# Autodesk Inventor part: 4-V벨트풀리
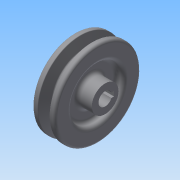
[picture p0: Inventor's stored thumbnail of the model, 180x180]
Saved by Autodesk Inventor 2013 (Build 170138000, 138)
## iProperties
Created: 2015-03
Part Number: 4-V벨트풀리
Material: 일반
Document SubType Name: Modeling
Designer: Administrator
Density: 1 g/cm^3
Author: Administrator
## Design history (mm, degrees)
sketch "스케치1"
  geometry: L1 (0, 0)-(25, 0); L2 (0, 0)-(0, 11); L3 (0, 11)-(6, 11); L4 (6, 11)-(6, 21.5); L5 (6, 21.5)-(0, 21.5); L6 (0, 21.5)-(0, 35.2); L7 (0, 35.2)-(4.675, 35.2); L8 (4.675, 35.2)-(7.426, 26.2); L9 (7.426, 26.2)-(11.574, 26.2); L10 (11.574, 26.2)-(14.325, 35.2); L11 (14.325, 35.2)-(19, 35.2); L12 (19, 35.2)-(19, 21.5); L13 (19, 21.5)-(13, 21.5); L14 (13, 21.5)-(13, 11); L15 (13, 11)-(25, 11); L16 (25, 11)-(25, 0); 2 further points
  constraints: 32 end point, 9 parallel, 4 collinear, 4 equal length, 2 perpendicular, 2 point on line, 1 horizontal, 1 horizontal alignment
  dimensions: "d0" = 25 distance of L1.start L1.end; "d1" = 22 diameter of L3 L1; "d2" = 43 diameter of L5 L1; "d3" = 6 distance of L4.end L5.end; "d4" = 19 distance between parallel lines of L12 L6; "d5" = 6 distance of L12.end L13.end; "d6" = 65 diameter of point (5.5, 32.5) L1; "d7" = 34 deg angle of L10 L8; "d8" = 6.3 distance from line of L9 point (5.5, 32.5); "d9" = 2.7 distance from line of L7 point (5.5, 32.5); "d10" = 8 distance of point (13.5, 32.5) point (5.5, 32.5)
revolve "회전1" sketch "스케치1" stored, may be unused: angle "d11" = 90 deg
sketch "스케치2"
  geometry: L1 (-2, 5.123)-(-2, 7.3); L2 (-2, 7.3)-(2, 7.3); L3 (2, 7.3)-(2, 5.123); C1 r 11 at (0, 0) reference; A1 r 5.5 centre (0, 0) between (-2, 5.123) and (2, 5.123)
  constraints: 6 end point, 2 parallel, 2 point on circle, 1 centre point, 1 coincident, 1 perpendicular, 1 vertical
  dimensions: "d12" = 11 diameter of A1; "d14" = 12.8 dimension on A1 L2; "d16" = 4 distance of L1.end L2.end
extrude "돌출1" cut sketch "스케치2" stored distance "d17" = 10; taper "d18" = 0 deg
fillet "모깎기1" dims "d19" = 2, "d20" = 0.5, "d21" = 1
fillet "모깎기2" dims "d22" = 3
node "솔리드1"
